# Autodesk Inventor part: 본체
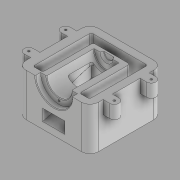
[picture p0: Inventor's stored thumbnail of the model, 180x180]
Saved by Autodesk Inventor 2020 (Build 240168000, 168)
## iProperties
Created: 2022-03
Part Number: 본체
Material: 일반
Document SubType Name: Modeling
Designer: Administrator
Density: 1 g/cm^3
Appearance: 기본값
Author: Administrator
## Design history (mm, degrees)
sketch "스케치1"
  geometry: L1 (-55, 55)-(55, 55); L2 (55, 55)-(55, -55); L3 (55, -55)-(-55, -55); L4 (-55, -55)-(-55, 55); L5 (-55, 55)-(55, -55); L6 (55, 55)-(-55, -55); 1 further point
  constraints: 12 end point, 2 midpoint, 2 parallel, 1 horizontal, 1 perpendicular
  dimensions: "d0" = 110 distance of L2.end L3.end; "d1" = 110 distance of L1.end L2.end
extrude "돌출1" new body sketch "스케치1" distance "d2" = 65; taper "d3" = 0 deg
sketch "스케치2"
  geometry: L1 (-73.452, 28)-(83.043, 28); L2 (55, 55)-(-55, 55) reference; L3 (-65, 35)-(-55, 35); L4 (-65, 21)-(-55, 21); L5 (-73.452, -28)-(83.043, -28); L6 (-65, 61.443)-(-65, 7.688); L7 (-55, 55)-(-55, -55) reference; L8 (0, 55)-(0, 0); L9 (65, 35)-(55, 35); L10 (65, 21)-(55, 21); L11 (-55, 0)-(32.738, 0); L12 (-65, -35)-(-55, -35); L13 (-65, -21)-(-55, -21); L14 (65, -21)-(55, -21); L15 (65, -35)-(55, -35); L16 (55, -55)-(55, 55) reference; L17 (-55, 35)-(-55, 21); L18 (-55, -21)-(-55, -35); L19 (55, 35)-(55, 21); L20 (55, -21)-(55, -35); A1 r 7 centre (-65, 28) between (-65, 35) and (-65, 21); A2 r 7 centre (65, 28) between (65, 21) and (65, 35); A3 r 7 centre (-65, -28) between (-65, -21) and (-65, -35); A4 r 7 centre (65, -28) between (65, -35) and (65, -21); 2 further points
  constraints: 34 end point, 15 symmetric about line, 8 point on circle, 6 point on line, 5 horizontal, 4 centre point, 4 collinear, 2 midpoint, 2 vertical, 3 other
  dimensions: "d4" = 27 distance between parallel lines of L1 L2; "d7" = 56 distance between parallel lines of L5 L1; "d9" = 7 radius of A1; "d10" = 10 distance between parallel lines of L6 L7
extrude "돌출2" join sketch "스케치2" distance "d11" = 20; taper "d12" = 0 deg
sketch "스케치3"
  geometry: A1 r 7 centre (65, 28) between (65, 21) and (65, 35) reference; A2 r 7 centre (65, -28) between (65, -35) and (65, -21) reference; A3 r 7 centre (-65, 28) between (-65, 35) and (-65, 21) reference; A4 r 7 centre (-65, -28) between (-65, -21) and (-65, -35) reference; 5 further points
  constraints: 4 coincident
hole "구멍1" sketch "스케치3" at (65, 28), (65, -28), (-65, 28), (-65, -28) diameter "d13" = 3.242; stored, may be unused: countersink angle "d17" = 90 deg, drill point angle "d19" = 118 deg; dims "d14" = 9, "d15" = 4, "d16" = 2, "d18" = 11
sketch "스케치4"
  geometry: L1 (-41.947, -44.668)-(-41.947, 43.794); L2 (-41.947, 43.794)-(43.822, 43.794); L3 (43.822, 43.794)-(43.822, -44.668); L4 (43.822, -44.668)-(28.822, -44.668); L5 (28.822, -44.668)-(28.822, 31.794); L6 (28.822, 31.794)-(-26.947, 31.794); L7 (-26.947, 31.794)-(-26.947, -44.668); L8 (-26.947, -44.668)-(-41.947, -44.668); 1 further point
  constraints: 16 end point, 7 perpendicular, 1 point on line, 1 vertical
  dimensions: "d20" = 15 distance of L7.end L1.start; "d21" = 15 distance of L3.end L4.end; "d22" = 12 distance between parallel lines of L6 L2
extrude "돌출3" cut sketch "스케치4" extent not by distance; stored distance "d23" = 60; taper "d24" = 0 deg
fillet "모깎기1" dims "d25" = 13
fillet "모깎기2" dims "d26" = 3
sketch "스케치5"
  geometry: L1 (0, 65)-(84, 65) reference; C1 r 28 at (42, 65); 1 further point
  constraints: 1 centre point, 1 midpoint
  dimensions: "d27" = 28 radius of C1
extrude "돌출4" cut sketch "스케치5" distance "d28" = 8; taper "d29" = 0 deg
sketch "스케치6"
  geometry: C1 r 19 at (42, 64.741); 1 further point
  constraints: 1 centre point
  dimensions: "d30" = 19 radius of C1
extrude "돌출5" cut sketch "스케치6" distance "d31" = 72; taper "d32" = 0 deg
node "작업 평면1"
sketch "스케치7"
  geometry: L1 (-25.822, -31.794)-(23.947, -31.794) reference; L2 (9.809, -25)-(7.5, -29); L3 (7.5, -29)-(0, -29); L4 (0, -29)-(0, -25); L5 (9.809, -25)-(0, -25); L6 (18.998, -25)-(-18.998, -25) reference; 2 further points
  constraints: 8 end point, 2 midpoint, 1 horizontal, 1 parallel, 1 perpendicular
  dimensions: "d34" = 30 deg angle of L4 L2; "d35" = 7.5 distance of L2.end L3.end; "d36" = 4 distance between parallel lines of L5 L3
revolve "회전1" sketch "스케치7" stored, may be unused: angle "d37" = 90 deg
fillet "모깎기3" dims "d38" = 1
chamfer "모따기1" distance "d39" = 1; stored, may be unused: second distance "d40" = 2, angle "d41" = 60 deg
sketch "스케치8"
  geometry: L1 (62.741, -19)-(28.006, -19); L2 (28.006, -19)-(28.006, 19); L3 (28.006, 19)-(62.741, 19); L4 (62.741, 19)-(62.741, -19); L5 (65, 46)-(65, 46) reference; L6 (65, -24)-(65, 46) reference; L7 (65, -24)-(65, -24) reference; L8 (65, 46)-(65, -24) reference; L9 (65, -24)-(65, -25) reference; L10 (65, -25)-(65, -25) reference; L11 (65, -25)-(65, -24) reference; L12 (65, -24)-(65, -24) reference; L13 (65, -25)-(65, -25) reference; L14 (65, -25)-(65, -25) reference; L15 (45.741, 46)-(45.741, -24) reference; L16 (65, -24)-(65, 46) reference; L17 (46.741, -25)-(65, -25) reference; L18 (28.006, 19)-(17.096, 55); L19 (28.006, -19)-(7.252, 55); L20 (65, 55)-(0, 55) reference; A1 r 1 centre (46.741, -24) between (45.741, -24) and (46.741, -25) reference; 3 further points
  constraints: 12 end point, 2 parallel, 2 point on line, 1 horizontal, 1 perpendicular
  dimensions: "d42" = 6 distance between parallel lines of L17 L1; "d43" = 38 distance between parallel lines of L3 L1; "d46" = 34 diameter of L4 L15
revolve "회전2" sketch "스케치8" stored, may be unused: angle "d45" = 90 deg
sketch "스케치9" dims "d47" = 46
  geometry: L1 (35.077, 65)-(48.923, 65) reference; 3 further points
  constraints: 1 midpoint, 1 vertical alignment, 2 other
hole "구멍2" sketch "스케치9" at (42, 42) diameter "d48" = 3.242; stored, may be unused: countersink angle "d52" = 90 deg, drill point angle "d54" = 118 deg; dims "d49" = 9, "d50" = 4, "d51" = 2, "d53" = 11
sketch "스케치10"
  geometry: L1 (25, 27.082)-(59, 27.082); L2 (59, 27.082)-(59, 10.082); L3 (59, 10.082)-(25, 10.082); L4 (25, 10.082)-(25, 27.082); L5 (0, 0)-(84, 0) reference; 3 further points
  constraints: 8 end point, 2 midpoint, 2 parallel, 1 horizontal, 1 perpendicular, 1 vertical alignment
  dimensions: "d55" = 34 distance of L2.end L3.end; "d56" = 17 distance of L1.end L2.end
sketch "스케치11"
  geometry: L1 (28.188, -31.794)-(10.519, 34.15); L2 (10.519, 34.15)-(0, 34.15); L3 (0, 42)-(0, -42) reference; L4 (65, 55)-(0, 55) reference; L5 (0, 42)-(0, 55) reference; L6 (0, -55)-(0, -42) reference; L7 (0, -31.794)-(65, -31.794) reference; L8 (10.108, 55)-(21.855, 11.16); L9 (28.188, -31.794)-(0, -31.794); 3 further points
  constraints: 8 end point, 4 point on line, 1 horizontal, 1 parallel, 1 perpendicular
  dimensions: "d57" = 75 deg angle of L1 L7; "d58" = 5 distance between parallel lines of L8 L1
extrude "돌출6" cut sketch "스케치11" stored distance "d59" = 60; taper "d60" = 0 deg
fillet "모깎기4" dims "d61" = 3
fillet "모깎기5" dims "d66" = 3
fillet "모깎기6" dims "d67" = 3
sketch "스케치13"
  geometry: L1 (11.114, 31.926)-(27.592, -29.57) reference; L2 (10.108, 55)-(32.422, -28.276); L3 (27.708, 55)-(48.843, -23.876); L4 (65, 55)-(0, 55) reference; L5 (31.741, -19)-(50.898, -19) reference; L6 (28.741, -16)-(28.741, 16) reference; A1 r 3 centre (31.741, -16) between (28.741, -16) and (31.741, -19) reference; 3 further points
  constraints: 4 end point, 2 parallel, 2 point on line
  dimensions: "d68" = 5 distance between parallel lines of L1 L2; "d69" = 17 distance between parallel lines of L2 L3
extrude "돌출8" cut sketch "스케치13" stored distance "d70" = 34; taper "d71" = 0 deg
node "솔리드1"
node "투영된 루프1"
node "투영된 루프2"
node "투영된 루프3"
feature "A9D066F2-1C7D-4E18-AEED-F7BC21143FA4" dims "d13" = 3.242, "d14" = 9, "d15" = 4, "d16" = 2, "d17" = 90 deg, "d18" = 11, "d19" = 118 deg
other parameters: "d33" = 65, "d62" = 5, "d63" = 17
